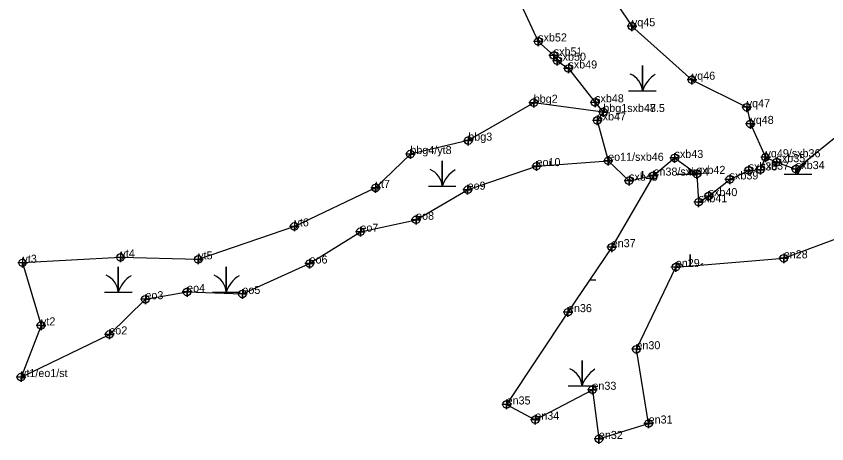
# Model space of a CAD drawing. Extents: x 2071991 to 2268989, y 436479 to 469629.
# Drawn here: x 2247031 to 2247535, y 439256 to 439521 of the extents above; entities that cross this region are included whole.
import ezdxf

# ---------------------------------------------------------------- set-up
doc = ezdxf.new("R2010")
doc.units = 0
for name, color, linetype in [('Exist Environmental Wetland Boundary', 7, 'Continuous'), ('Exist Environmental Wetland Boundary Cogo Comment', 7, 'Continuous'), ('Exist Environmental Wetland Boundary Cogo Point CELL', 7, 'Continuous'), ('Exist Hydro Jurisdictional Stream or Body of Water NEU Mitigable', 7, 'Continuous'), ('Exist Hydro Jurisdictional Stream or Body of Water NEU Mitigable Cogo Comment', 7, 'Continuous'), ('Exist Hydro Jurisdictional Stream or Body of Water NEU Mitigable Cogo Point CELL', 7, 'Continuous'), ('Exist Hydro Swamp or Marsh', 7, 'Continuous')]:
    doc.layers.add(name, color=color, linetype=linetype)

msp = doc.modelspace()

# ---------------------------------------------------------------- linework, layer by layer
at = {"layer": 'Exist Environmental Wetland Boundary'}
for points in [[(2247231.25, 439809.83), (2247239.7, 439769.66), (2247252.32, 439740.15), (2247266.69, 439706.28), (2247281.21, 439685.16), (2247304.15, 439665.69), (2247318.38, 439645.69), (2247350.09, 439633.3), (2247360.61, 439598), (2247372.36, 439574.3), (2247395.45, 439542.63), (2247413.72, 439515.12), (2247451.01, 439481.89), (2247485.18, 439464.77), (2247487.44, 439454.45), (2247496.86, 439433.69)], [(2247395.91, 439461.8), (2247352.63, 439467.59), (2247311.9, 439444.02), (2247275.84, 439435.69), (2247254.22, 439414.66), (2247203.7, 439390.76), (2247143.81, 439370.23), (2247095.45, 439371.46), (2247034.46, 439368.09), (2247045.97, 439329.17), (2247033.54, 439297.07), (2247088.49, 439323.58), (2247110.95, 439345.45), (2247136.9, 439349.96), (2247171.31, 439348.75), (2247213.09, 439367.64), (2247244.73, 439387.42), (2247279.39, 439394.84), (2247311.49, 439413.52), (2247354.35, 439428.18), (2247398.93, 439431.48)], [(2247427.15, 439422.28), (2247401.16, 439377.8), (2247373.91, 439337.42), (2247335.73, 439280.04), (2247353.58, 439270.56), (2247389.14, 439289.16), (2247393.17, 439258.6), (2247424.12, 439268.2), (2247416.53, 439314.36), (2247441.03, 439365.47), (2247508.21, 439370.9), (2247546.26, 439385.16)]]:
    msp.add_lwpolyline(points, dxfattribs=at)
at = {"layer": 'Exist Environmental Wetland Boundary Cogo Point CELL'}
for points in [[(2247413.72, 439518.12), (2247413.72, 439512.12), (2247413.72, 439515.12), (2247416.72, 439515.12), (2247410.72, 439515.12)], [(2247451.01, 439484.89), (2247451.01, 439478.89), (2247451.01, 439481.89), (2247454.01, 439481.89), (2247448.01, 439481.89)], [(2247352.63, 439470.59), (2247352.63, 439464.59), (2247352.63, 439467.59), (2247355.63, 439467.59), (2247349.63, 439467.59)], [(2247395.91, 439464.8), (2247395.91, 439458.8), (2247395.91, 439461.8), (2247398.91, 439461.8), (2247392.91, 439461.8)], [(2247485.18, 439467.77), (2247485.18, 439461.77), (2247485.18, 439464.77), (2247488.18, 439464.77), (2247482.18, 439464.77)], [(2247487.44, 439457.45), (2247487.44, 439451.45), (2247487.44, 439454.45), (2247490.44, 439454.45), (2247484.44, 439454.45)], [(2247311.9, 439447.02), (2247311.9, 439441.02), (2247311.9, 439444.02), (2247314.9, 439444.02), (2247308.9, 439444.02)], [(2247275.84, 439438.69), (2247275.84, 439432.69), (2247275.84, 439435.69), (2247278.84, 439435.69), (2247272.84, 439435.69)], [(2247398.93, 439434.48), (2247398.93, 439428.48), (2247398.93, 439431.48), (2247401.93, 439431.48), (2247395.93, 439431.48)], [(2247496.86, 439436.69), (2247496.86, 439430.69), (2247496.86, 439433.69), (2247499.86, 439433.69), (2247493.86, 439433.69)], [(2247354.35, 439431.18), (2247354.35, 439425.18), (2247354.35, 439428.18), (2247357.35, 439428.18), (2247351.35, 439428.18)], [(2247427.15, 439425.28), (2247427.15, 439419.28), (2247427.15, 439422.28), (2247430.15, 439422.28), (2247424.15, 439422.28)], [(2247254.22, 439417.66), (2247254.22, 439411.66), (2247254.22, 439414.66), (2247257.22, 439414.66), (2247251.22, 439414.66)], [(2247311.49, 439416.52), (2247311.49, 439410.52), (2247311.49, 439413.52), (2247314.49, 439413.52), (2247308.49, 439413.52)], [(2247203.7, 439393.76), (2247203.7, 439387.76), (2247203.7, 439390.76), (2247206.7, 439390.76), (2247200.7, 439390.76)], [(2247279.39, 439397.84), (2247279.39, 439391.84), (2247279.39, 439394.84), (2247282.39, 439394.84), (2247276.39, 439394.84)], [(2247244.73, 439390.42), (2247244.73, 439384.42), (2247244.73, 439387.42), (2247247.73, 439387.42), (2247241.73, 439387.42)], [(2247401.16, 439380.8), (2247401.16, 439374.8), (2247401.16, 439377.8), (2247404.16, 439377.8), (2247398.16, 439377.8)], [(2247095.45, 439374.46), (2247095.45, 439368.46), (2247095.45, 439371.46), (2247098.45, 439371.46), (2247092.45, 439371.46)], [(2247143.81, 439373.23), (2247143.81, 439367.23), (2247143.81, 439370.23), (2247146.81, 439370.23), (2247140.81, 439370.23)], [(2247508.21, 439373.9), (2247508.21, 439367.9), (2247508.21, 439370.9), (2247511.21, 439370.9), (2247505.21, 439370.9)], [(2247034.46, 439371.09), (2247034.46, 439365.09), (2247034.46, 439368.09), (2247037.46, 439368.09), (2247031.46, 439368.09)], [(2247213.09, 439370.64), (2247213.09, 439364.64), (2247213.09, 439367.64), (2247216.09, 439367.64), (2247210.09, 439367.64)], [(2247441.03, 439368.47), (2247441.03, 439362.47), (2247441.03, 439365.47), (2247444.03, 439365.47), (2247438.03, 439365.47)], [(2247136.9, 439352.96), (2247136.9, 439346.96), (2247136.9, 439349.96), (2247139.9, 439349.96), (2247133.9, 439349.96)], [(2247110.95, 439348.45), (2247110.95, 439342.45), (2247110.95, 439345.45), (2247113.95, 439345.45), (2247107.95, 439345.45)], [(2247171.31, 439351.75), (2247171.31, 439345.75), (2247171.31, 439348.75), (2247174.31, 439348.75), (2247168.31, 439348.75)], [(2247373.91, 439340.42), (2247373.91, 439334.42), (2247373.91, 439337.42), (2247376.91, 439337.42), (2247370.91, 439337.42)], [(2247045.97, 439332.17), (2247045.97, 439326.17), (2247045.97, 439329.17), (2247048.97, 439329.17), (2247042.97, 439329.17)], [(2247088.49, 439326.58), (2247088.49, 439320.58), (2247088.49, 439323.58), (2247091.49, 439323.58), (2247085.49, 439323.58)], [(2247416.53, 439317.36), (2247416.53, 439311.36), (2247416.53, 439314.36), (2247419.53, 439314.36), (2247413.53, 439314.36)], [(2247033.54, 439300.07), (2247033.54, 439294.07), (2247033.54, 439297.07), (2247036.54, 439297.07), (2247030.54, 439297.07)], [(2247389.14, 439292.16), (2247389.14, 439286.16), (2247389.14, 439289.16), (2247392.14, 439289.16), (2247386.14, 439289.16)], [(2247335.73, 439283.04), (2247335.73, 439277.04), (2247335.73, 439280.04), (2247338.73, 439280.04), (2247332.73, 439280.04)], [(2247353.58, 439273.56), (2247353.58, 439267.56), (2247353.58, 439270.56), (2247356.58, 439270.56), (2247350.58, 439270.56)], [(2247424.12, 439271.2), (2247424.12, 439265.2), (2247424.12, 439268.2), (2247427.12, 439268.2), (2247421.12, 439268.2)], [(2247393.17, 439261.6), (2247393.17, 439255.6), (2247393.17, 439258.6), (2247396.17, 439258.6), (2247390.17, 439258.6)]]:
    msp.add_lwpolyline(points, dxfattribs=at)
for centre in [(2247413.72, 439515.12), (2247451.01, 439481.89), (2247352.63, 439467.59), (2247395.91, 439461.8), (2247485.18, 439464.77), (2247487.44, 439454.45), (2247311.9, 439444.02), (2247275.84, 439435.69), (2247398.93, 439431.48), (2247496.86, 439433.69), (2247354.35, 439428.18), (2247427.15, 439422.28), (2247254.22, 439414.66), (2247311.49, 439413.52), (2247279.39, 439394.84), (2247203.7, 439390.76), (2247244.73, 439387.42), (2247401.16, 439377.8), (2247095.45, 439371.46), (2247508.21, 439370.9), (2247034.46, 439368.09), (2247143.81, 439370.23), (2247213.09, 439367.64), (2247441.03, 439365.47), (2247136.9, 439349.96), (2247171.31, 439348.75), (2247110.95, 439345.45), (2247373.91, 439337.42), (2247045.97, 439329.17), (2247088.49, 439323.58), (2247416.53, 439314.36), (2247033.54, 439297.07), (2247389.14, 439289.16), (2247335.73, 439280.04), (2247353.58, 439270.56), (2247424.12, 439268.2), (2247393.17, 439258.6)]:
    msp.add_circle(centre, 2.34, dxfattribs=at)
at = {"layer": 'Exist Hydro Jurisdictional Stream or Body of Water NEU Mitigable'}
msp.add_lwpolyline([(2247344.84, 439528.39), (2247355.41, 439505.68), (2247365.09, 439496.95), (2247367.26, 439493.73), (2247374.21, 439488.89), (2247390.81, 439467.83), (2247395.91, 439461.8), (2247392.18, 439456.62), (2247398.93, 439431.48), (2247411.94, 439419.14), (2247427.15, 439422.28), (2247440.26, 439433.26), (2247454.03, 439423.34), (2247455.24, 439405.77), (2247461.46, 439409.54), (2247474.55, 439419.91), (2247486.35, 439425.51), (2247493.63, 439425.97), (2247496.86, 439433.69), (2247503.7, 439430.63), (2247515.81, 439426.34), (2247539.52, 439445.63)], dxfattribs=at)
at = {"layer": 'Exist Hydro Jurisdictional Stream or Body of Water NEU Mitigable Cogo Point CELL'}
for points in [[(2247355.41, 439508.68), (2247355.41, 439502.68), (2247355.41, 439505.68), (2247358.41, 439505.68), (2247352.41, 439505.68)], [(2247365.09, 439499.95), (2247365.09, 439493.95), (2247365.09, 439496.95), (2247368.09, 439496.95), (2247362.09, 439496.95)], [(2247367.26, 439496.73), (2247367.26, 439490.73), (2247367.26, 439493.73), (2247370.26, 439493.73), (2247364.26, 439493.73)], [(2247374.21, 439491.89), (2247374.21, 439485.89), (2247374.21, 439488.89), (2247377.21, 439488.89), (2247371.21, 439488.89)], [(2247390.81, 439470.83), (2247390.81, 439464.83), (2247390.81, 439467.83), (2247393.81, 439467.83), (2247387.81, 439467.83)], [(2247395.91, 439464.8), (2247395.91, 439458.8), (2247395.91, 439461.8), (2247398.91, 439461.8), (2247392.91, 439461.8)], [(2247392.18, 439459.62), (2247392.18, 439453.62), (2247392.18, 439456.62), (2247395.18, 439456.62), (2247389.18, 439456.62)], [(2247440.26, 439436.26), (2247440.26, 439430.26), (2247440.26, 439433.26), (2247443.26, 439433.26), (2247437.26, 439433.26)], [(2247503.7, 439433.63), (2247503.7, 439427.63), (2247503.7, 439430.63), (2247506.7, 439430.63), (2247500.7, 439430.63)], [(2247493.63, 439428.97), (2247493.63, 439422.97), (2247493.63, 439425.97), (2247496.63, 439425.97), (2247490.63, 439425.97)], [(2247515.81, 439429.34), (2247515.81, 439423.34), (2247515.81, 439426.34), (2247518.81, 439426.34), (2247512.81, 439426.34)], [(2247454.03, 439426.34), (2247454.03, 439420.34), (2247454.03, 439423.34), (2247457.03, 439423.34), (2247451.03, 439423.34)], [(2247486.35, 439428.51), (2247486.35, 439422.51), (2247486.35, 439425.51), (2247489.35, 439425.51), (2247483.35, 439425.51)], [(2247411.94, 439422.14), (2247411.94, 439416.14), (2247411.94, 439419.14), (2247414.94, 439419.14), (2247408.94, 439419.14)], [(2247474.55, 439422.91), (2247474.55, 439416.91), (2247474.55, 439419.91), (2247477.55, 439419.91), (2247471.55, 439419.91)], [(2247455.24, 439408.77), (2247455.24, 439402.77), (2247455.24, 439405.77), (2247458.24, 439405.77), (2247452.24, 439405.77)], [(2247461.46, 439412.54), (2247461.46, 439406.54), (2247461.46, 439409.54), (2247464.46, 439409.54), (2247458.46, 439409.54)]]:
    msp.add_lwpolyline(points, dxfattribs=at)
for centre in [(2247355.41, 439505.68), (2247365.09, 439496.95), (2247367.26, 439493.73), (2247374.21, 439488.89), (2247390.81, 439467.83), (2247395.91, 439461.8), (2247392.18, 439456.62), (2247440.26, 439433.26), (2247503.7, 439430.63), (2247515.81, 439426.34), (2247454.03, 439423.34), (2247486.35, 439425.51), (2247493.63, 439425.97), (2247411.94, 439419.14), (2247474.55, 439419.91), (2247461.46, 439409.54), (2247455.24, 439405.77)]:
    msp.add_circle(centre, 2.34, dxfattribs=at)
at = {"layer": 'Exist Hydro Swamp or Marsh'}
msp.add_line((2247387.43, 439357.44), (2247391.26, 439357.44), dxfattribs=at)
for points in [[(2247411.63, 439474.97), (2247420.23, 439474.97), (2247420.23, 439490.75), (2247420.23, 439474.97), (2247428.83, 439474.97)], [(2247287.03, 439415.64), (2247295.63, 439415.64), (2247295.63, 439431.42), (2247295.63, 439415.64), (2247304.23, 439415.64)], [(2247362.83, 439428.81), (2247362.83, 439431.42), (2247362.83, 439428.81)], [(2247420.23, 439420.85), (2247420.23, 439424.97), (2247420.23, 439420.85)], [(2247441.26, 439423.23), (2247449.86, 439423.23), (2247449.86, 439426.34)], [(2247449.86, 439426.34), (2247449.86, 439423.23), (2247454.04, 439423.23)], [(2247508.47, 439423.23), (2247517.07, 439423.23), (2247517.07, 439427.36)], [(2247517.07, 439427.36), (2247517.07, 439423.23), (2247525.67, 439423.23)], [(2247449.86, 439366.18), (2247449.86, 439373.23), (2247449.86, 439366.18)], [(2247085.42, 439349.86), (2247094.02, 439349.86), (2247094.02, 439365.64), (2247094.02, 439349.86), (2247102.62, 439349.86)], [(2247152.62, 439349.86), (2247161.22, 439349.86), (2247161.22, 439365.64), (2247161.22, 439349.86), (2247169.82, 439349.86)], [(2247374.06, 439291.66), (2247382.66, 439291.66), (2247382.66, 439307.44), (2247382.66, 439291.66), (2247391.26, 439291.66)]]:
    msp.add_lwpolyline(points, dxfattribs=at)
for centre, radius, start, end in [((2247407.97, 439474.08), 12.3, 4.1403, 67.535), ((2247438.47, 439468.91), 19.22, 122.1274, 161.6222), ((2247535.31, 439417.16), 19.22, 122.1274, 161.6222), ((2247283.36, 439414.76), 12.3, 4.1403, 67.535), ((2247313.87, 439409.58), 19.22, 122.1274, 161.6222), ((2247437.6, 439422.34), 12.3, 4.1403, 22.1525), ((2247468.11, 439417.16), 19.22, 153.8602, 161.6222), ((2247504.8, 439422.34), 12.3, 4.1403, 20.926), ((2247407.97, 439408.3), 12.3, 64.5226, 67.535), ((2247437.6, 439356.56), 12.3, 49.0278, 67.535), ((2247468.11, 439351.38), 19.22, 122.1274, 127.0835), ((2247081.75, 439348.97), 12.3, 4.1403, 67.535), ((2247112.26, 439343.8), 19.22, 122.1274, 161.6222), ((2247148.95, 439348.97), 12.3, 4.1403, 67.535), ((2247179.46, 439343.8), 19.22, 122.1274, 161.6222), ((2247370.39, 439290.78), 12.3, 4.1403, 67.535), ((2247400.9, 439285.6), 19.22, 122.1274, 161.6222)]:
    msp.add_arc(centre, radius, start, end, dxfattribs=at)

# ---------------------------------------------------------------- texts
at = {"layer": 'Exist Environmental Wetland Boundary Cogo Comment'}
for s, p in [('yq45', (2247413.72, 439515.12)), ('yq46', (2247451.01, 439481.89)), ('bbg2', (2247352.63, 439467.59)), ('yq47', (2247485.18, 439464.77)), ('yq48', (2247487.44, 439454.45)), ('bbg3', (2247311.9, 439444.02)), ('bbg4/yt8', (2247275.84, 439435.69)), ('eo10', (2247354.35, 439428.18)), ('yt7', (2247254.22, 439414.66)), ('eo9', (2247311.49, 439413.52)), ('eo8', (2247279.39, 439394.84)), ('yt6', (2247203.7, 439390.76)), ('eo7', (2247244.73, 439387.42)), ('en37', (2247401.16, 439377.8)), ('yt3', (2247034.46, 439368.09)), ('yt4', (2247095.45, 439371.46)), ('yt5', (2247143.81, 439370.23)), ('en28', (2247508.21, 439370.9)), ('eo6', (2247213.09, 439367.64)), ('en29', (2247441.03, 439365.47)), ('eo4', (2247136.9, 439349.96)), ('eo5', (2247171.31, 439348.75)), ('eo3', (2247110.95, 439345.45)), ('en36', (2247373.91, 439337.42)), ('yt2', (2247045.97, 439329.17)), ('eo2', (2247088.49, 439323.58)), ('en30', (2247416.53, 439314.36)), ('yt1/eo1/st', (2247033.54, 439297.07)), ('en33', (2247389.14, 439289.16)), ('en35', (2247335.73, 439280.04)), ('en34', (2247353.58, 439270.56)), ('en31', (2247424.12, 439268.2)), ('en32', (2247393.17, 439258.6))]:
    msp.add_text(s, height=5, dxfattribs=at).set_placement(p)
at = {"layer": 'Exist Hydro Jurisdictional Stream or Body of Water NEU Mitigable Cogo Comment'}
for s, p in [('sxb52', (2247355.41, 439505.68)), ('sxb51', (2247365.09, 439496.95)), ('sxb50', (2247367.26, 439493.73)), ('sxb49', (2247374.21, 439488.89)), ('sxb48', (2247390.81, 439467.83)), ('bbg1sxb48.', (2247395.91, 439461.8)), ('bbg1sxb47.5', (2247395.91, 439461.8)), ('sxb47', (2247392.18, 439456.62)), ('yq49/sxb36', (2247496.86, 439433.69)), ('eo11/sxb46', (2247398.93, 439431.48)), ('sxb43', (2247440.26, 439433.26)), ('sxb35', (2247503.7, 439430.63)), ('sxb42', (2247454.03, 439423.34)), ('sxb38', (2247486.35, 439425.51)), ('sxb37', (2247493.63, 439425.97)), ('sxb34', (2247515.81, 439426.34)), ('sxb45', (2247411.94, 439419.14)), ('en38/sxb44', (2247427.15, 439422.28)), ('sxb39', (2247474.55, 439419.91)), ('sxb40', (2247461.46, 439409.54)), ('sxb41', (2247455.24, 439405.77))]:
    msp.add_text(s, height=5, dxfattribs=at).set_placement(p)

doc.saveas('drawing.dxf')
